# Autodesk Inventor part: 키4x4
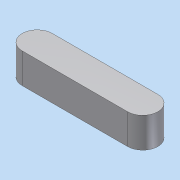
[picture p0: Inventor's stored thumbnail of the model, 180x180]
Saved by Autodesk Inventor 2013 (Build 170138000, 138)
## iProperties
Company: 한국ATC센터
Created: 2011-07
Part Number: 키4x4
Document SubType Name: Modeling
Designer: KYOUNG IL JANG
Density: 7.86 g/cm^3
Mass: 2.15573 g
Surface Area: 2.99398 cm^2
Volume: 0.274265 cm^3
Vendor: CBT Solutions
Material: 강, 연강
Author: KYOUNG IL JANG
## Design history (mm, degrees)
sketch "스케치1"
  geometry: L1 (0, 2)-(14, 2); L2 (0, -2)-(14, -2); A1 r 2 centre (0, 0) between (0, 2) and (0, -2); A2 r 2 centre (14, 0) between (14, -2) and (14, 2); 1 further point
  constraints: 4 end point, 4 point on circle, 3 tangent, 2 centre point, 1 coincident, 1 equal radius, 1 horizontal alignment, 1 parallel
  dimensions: "d0" = 4 distance between parallel lines of L2 L1; "d1" = 18 dimension on A2 A1
extrude "돌출1" new body sketch "스케치1" distance "d2" = 4; taper "d3" = 0 deg
node "솔리드1"
